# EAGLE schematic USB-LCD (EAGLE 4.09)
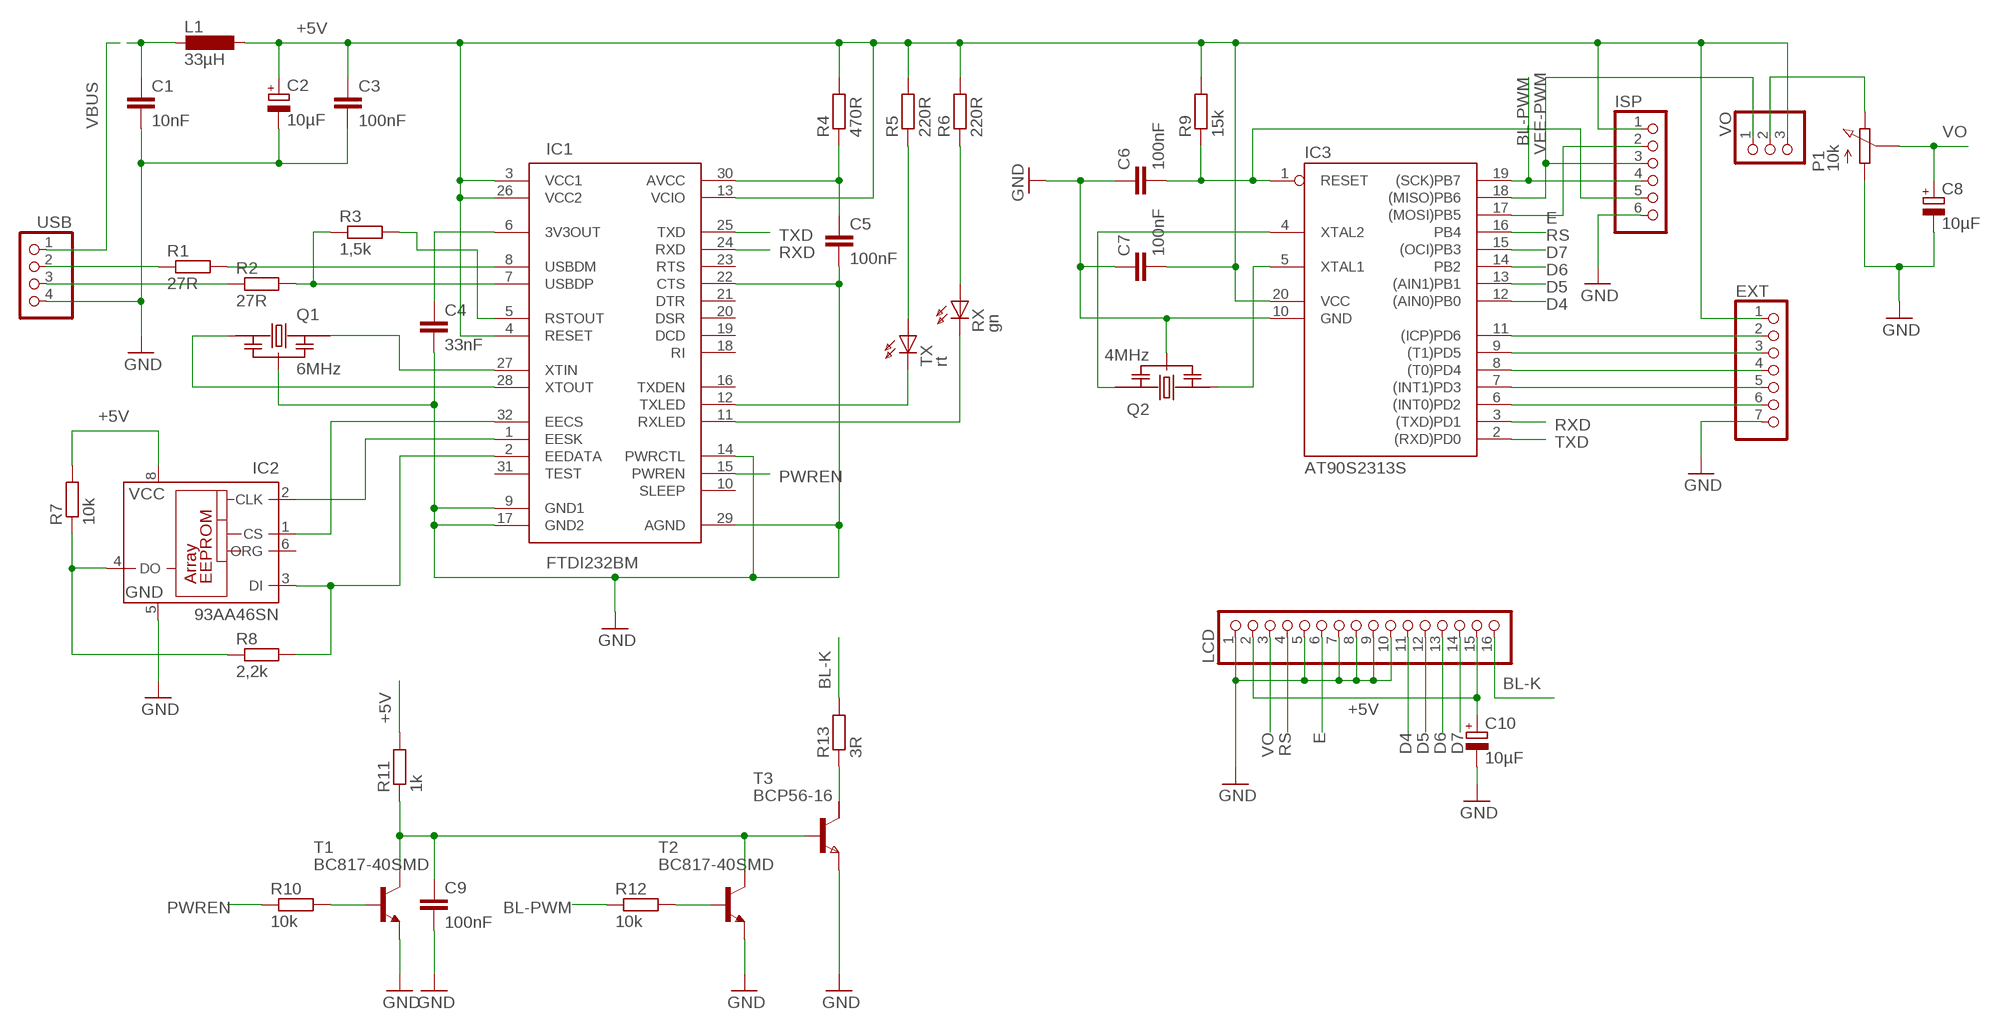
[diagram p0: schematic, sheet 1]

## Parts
C1  10nF  C-EUC1206  [C1206]
C2  10µF  CPOL-EUC/6032-28R  [C/6032-28R]
C3  100nF  C-EUC0805K  [C0805K]
C4  33nF  C-EUC0805K  [C0805K]
C5  100nF  C-EUC0805K  [C0805K]
C6  100nF  C-EUC0805K  [C0805K]
C7  100nF  C-EUC0805K  [C0805K]
C8  10µF  CPOL-EUC/6032-28R  [C/6032-28R]
C9  100nF  C-EUC0805K  [C0805K]
C10  10µF  CPOL-EUC/6032-28R  [C/6032-28R]
EXT  PINHD-1X7  [1X07]
IC1  FTDI232BM  FT232BM  [QFP-32]
IC2  93AA46SN  [SO-08]
IC3  AT90S2313S  [SO-20L]
ISP  PINHD-1X6  [1X06]
L1  33µH  L-EU0207/10  [0207/10]
LCD  PINHD-1X16  [1X16]
P1  10k  PC25  [PC25]
Q1  6MHz  CSTCC  [CSTCC]
Q2  4MHz  CSTCC  [CSTCC]
R1  27R  R-EU_R0805  [R0805]
R2  27R  R-EU_R0805  [R0805]
R3  1,5k  R-EU_R0805  [R0805]
R4  470R  R-EU_R0805  [R0805]
R5  220R  R-EU_R0805  [R0805]
R6  220R  R-EU_R0805  [R0805]
R7  10k  R-EU_R0805  [R0805]
R8  2,2k  R-EU_R0805  [R0805]
R9  15k  R-EU_R0805  [R0805]
R10  10k  R-EU_R0805  [R0805]
R11  1k  R-EU_R0805  [R0805]
R12  10k  R-EU_R0805  [R0805]
R13  3R  R-EU_R1206  [R1206]
RX  gn  LEDSMT1206  [1206]
T1  BC817-40SMD  [SOT23-BEC]
T2  BC817-40SMD  [SOT23-BEC]
T3  BCP56-16  NPNSOT223  [SOT223]
TX  rt  LEDSMT1206  [1206]
USB  PINHD-1X4  [1X04]
VO  PINHD-1X3  [1X03]

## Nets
+5V: C2.+ C3.1 C7.2 C10.+ EXT.1 IC1.3(VCC1) IC1.4(RESET) IC1.13(VCIO) IC1.26(VCC2) IC2.8(VCC) IC3.20(VCC) ISP.1 L1.1 LCD.2 LCD.15 R4.2 R5.2 R6.2 R7.2 R9.2 R11.2 VO.3
BL-K: LCD.16 R13.2
BL-PWM: IC3.19((SCK)PB7) ISP.4 R12.1
D4: IC3.12((AIN0)PB0) LCD.11
D5: IC3.13((AIN1)PB1) LCD.12
D6: IC3.14(PB2) LCD.13
D7: IC3.15((OCI)PB3) LCD.14
E: IC3.17((MOSI)PB5) ISP.2 LCD.6
GND: C1.2 C2.- C3.2 C4.2 C5.2 C6.1 C7.1 C8.- C9.2 C10.- EXT.7 IC1.9(GND1) IC1.14(PWRCTL) IC1.17(GND2) IC1.22(CTS) IC1.29(AGND) IC2.5(GND) IC3.10(GND) ISP.6 LCD.1 LCD.5 LCD.7 LCD.8 LCD.9 LCD.10 P1.A Q1.P$2(GND) Q2.P$2(GND) T1.E T2.E T3.3(E) USB.4
N$1: R1.1 USB.2
N$2: R2.1 USB.3
N$3: IC1.8(USBDM) R1.2
N$4: C6.2 IC3.1(RESET) ISP.5 R9.1
N$5: IC1.12(TXLED) TX.C
N$6: C5.1 IC1.30(AVCC) R4.1
N$7: IC1.11(RXLED) RX.C
N$8: R5.1 TX.A
N$9: R6.1 RX.A
N$10: C4.1 IC1.6(3V3OUT)
N$11: IC2.4(DO) R7.1 R8.1
N$12: IC1.1(EESK) IC2.2(CLK)
N$13: C9.1 R11.1 T1.C T2.C T3.1(B)
N$14: IC1.32(EECS) IC2.1(CS)
N$15: IC1.2(EEDATA) IC2.3(DI) R8.2
N$16: IC1.27(XTIN) Q1.P$3
N$17: IC1.28(XTOUT) Q1.P$1
N$18: IC1.7(USBDP) R2.2 R3.1
N$19: IC1.5(RSTOUT) R3.2
N$20: EXT.2 IC3.11((ICP)PD6)
N$21: R10.2 T1.B
N$22: P1.E VO.2
N$23: EXT.3 IC3.9((T1)PD5)
N$24: EXT.4 IC3.8((T0)PD4)
N$25: EXT.5 IC3.7((INT1)PD3)
N$26: EXT.6 IC3.6((INT0)PD2)
N$28: R12.2 T2.B
N$29: IC3.5(XTAL1) Q2.P$1
N$30: IC3.4(XTAL2) Q2.P$3
N$31: R13.1 T3.2(C1)
PWREN: IC1.15(PWREN) R10.1
RS: IC3.16(PB4) LCD.4
RXD: IC1.24(RXD) IC3.3((TXD)PD1)
TXD: IC1.25(TXD) IC3.2((RXD)PD0)
VBUS: C1.1 L1.2 USB.1
VEE-PWM: IC3.18((MISO)PB6) ISP.3 VO.1
VO: C8.+ LCD.3 P1.S
Unconnected: IC1.10(SLEEP) IC1.16(TXDEN) IC1.18(RI) IC1.19(DCD) IC1.20(DSR) IC1.21(DTR) IC1.23(RTS) IC1.31(TEST) IC2.6(ORG) IC2.7(NU) T3.4(C2)

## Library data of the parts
C1 C3-C7 C9 = rcl:C-EU: CAPACITOR, European symbol
C2 C8 C10 = rcl:CPOL-EU: POLARIZED CAPACITOR, European symbol
EXT = pinhead:PINHD-1X7: PIN HEADER
IC1 = ftdi2:FT232BM: FT232BM USB-RS232 Wandler FTDI
IC2 = microchip:93*: Serial EPROM 1 K/2 K/4 K, low voltage, Microwire
IC3 = atmel:AT90S2313: MICROCONTROLLER 2 Kbytes FLASH 128 bytes SRAM 128 bytes EEPROM UART
ISP = pinhead:PINHD-1X6: PIN HEADER
L1 = rcl:L-EU: INDUCTOR, European symbol
LCD = pinhead:PINHD-1X16: PIN HEADER
P1 = pot-vitrohm:PC25: VITROHM POTENTIOMETER
Q1 Q2 = Barth:CSTCC
R1-R13 = rcl:R-EU_: RESISTOR, European symbol
RX TX = led:LED: LED
T1 T2 = transistor-npn:BC817*: NPN Transistor
T3 = zetex:NPNSOT223: NPN TRANSISTOR
USB = pinhead:PINHD-1X4: PIN HEADER
VO = pinhead:PINHD-1X3: PIN HEADER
